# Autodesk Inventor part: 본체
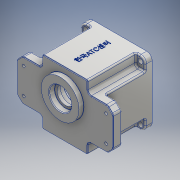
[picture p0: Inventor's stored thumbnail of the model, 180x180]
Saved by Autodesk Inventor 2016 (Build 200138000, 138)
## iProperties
Created: 2017-01
Part Number: 본체
Material: 알루미늄 6061
Document SubType Name: Modeling
Designer: Owner
Density: 2.7 g/cm^3
Appearance: 알루미늄 - 평지
Mass: 874.022 g
Surface Area: 769.042 cm^2
Volume: 323.712 cm^3
Author: Owner
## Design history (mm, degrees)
sketch "스케치1"
  geometry: L1 (47, 47)-(-47, 47); L2 (-47, 47)-(-47, -47); L3 (-47, -47)-(47, -47); L4 (47, -47)-(47, 47); L5 (47, 47)-(-47, -47); L6 (-47, 47)-(47, -47); 1 further point
  constraints: 12 end point, 2 midpoint, 2 parallel, 1 horizontal, 1 perpendicular
  dimensions: "d0" = 94 distance of L2.end L3.end; "d1" = 94 distance of L1.end L2.end
extrude "돌출1" new body sketch "스케치1" distance "d2" = 80; taper "d3" = 0 deg
sketch "스케치2"
  geometry: L1 (0, 0)-(85.477, 0); L2 (9, 0)-(9, 40); L3 (9, 40)-(71, 40); L4 (71, 40)-(71, 43); L5 (71, 43)-(80, 43); L6 (80, 43)-(80, 0); L7 (80, -47)-(80, 47) reference; L8 (0, -47)-(0, 47) reference; L9 (9, 0)-(80, 0)
  constraints: 14 end point, 3 perpendicular, 2 vertical, 1 collinear, 1 horizontal, 1 midpoint, 1 point on line
  dimensions: "d4" = 86 diameter of L5 L1; "d5" = 80 diameter of L3 L1; "d6" = 9 distance of L4.end L5.end; "d7" = 9 distance between parallel lines of L8 L2
revolve "회전1" sketch "스케치2" stored, may be unused: angle "d8" = 90 deg
sketch "스케치3"
  geometry: C1 r 21 at (0, -11); C2 r 15 at (0, 20); 1 further point
  constraints: 2 centre point, 2 vertical alignment
  dimensions: "d9" = 11 distance of point (0, 0) C1.centre; "d10" = 42 diameter of C1; "d13" = 20 distance of C2.centre point (0, 0); "d14" = 30 diameter of C2
extrude "돌출2" join sketch "스케치3" distance "d11" = 7; taper "d12" = 0 deg
hole "구멍1" diameter "d17" = 25; stored, may be unused: countersink angle "d21" = 90 deg, drill point angle "d23" = 118 deg; dims "d15" = 10, "d16" = 10, "d18" = 6, "d19" = 35, "d20" = 10, "d22" = 8
hole "구멍2" diameter "d26" = 19; stored, may be unused: countersink angle "d30" = 90 deg, drill point angle "d32" = 0 deg; dims "d27" = 6, "d28" = 22, "d29" = 7, "d31" = 8, "d33" = 10, "d34" = 10
sketch "스케치5"
  geometry: L1 (-47, 47)-(47, 47) reference; L2 (47, 47)-(47, -47) reference; L3 (47, -47)-(-47, -47) reference; L4 (-47, -47)-(-47, 47) reference; L5 (-33, 47)-(33, 47); L6 (33, 47)-(33, -47); L7 (33, -47)-(-33, -47); L8 (-33, -47)-(-33, 47); L9 (-33, 47)-(33, -47); L10 (33, 47)-(-33, -47); L11 (47, 47)-(47, -47) reference; L12 (-47, 30)-(47, 30); L13 (47, 30)-(47, -30); L14 (47, -30)-(-47, -30); L15 (-47, -30)-(-47, 30); L16 (-47, 30)-(47, -30); L17 (47, 30)-(-47, -30); 1 further point
  constraints: 24 end point, 4 midpoint, 4 parallel, 2 horizontal, 2 perpendicular, 1 horizontal alignment, 1 point on line
  dimensions: "d37" = 66 distance of L5.start L5.end; "d38" = 60 distance of L14.end L12.start
extrude "돌출3" cut sketch "스케치5" distance "d39" = 70; taper "d40" = 0 deg
sketch "스케치6"
  geometry: L1 (70, 30)-(70, -30); L2 (-70, -30)-(-70, 30); L3 (-70, 30)-(70, -30); L4 (70, 30)-(-70, -30); L5 (-47, -30)-(-47, 30) reference; L6 (47, 30)-(47, -30) reference; L7 (-47, 30)-(-47, -30); L8 (-70, 30)-(-47, 30); L9 (47, 30)-(70, 30); L10 (70, -30)-(47, -30); L11 (-47, -30)-(-70, -30); 1 further point
  constraints: 20 end point, 6 equal length, 2 horizontal, 2 midpoint, 2 perpendicular, 1 horizontal alignment
  dimensions: "d41" = 140 distance of L2.end L1.start
extrude "돌출4" join sketch "스케치6" distance "d42" = 13; taper "d43" = 0 deg
sketch "스케치7"
  geometry: C1 r 12.5 at (0, 11) reference; C2 r 27.5 at (0, 11); 1 further point
  constraints: 1 centre point, 1 coincident
  dimensions: "d44" = 55 diameter of C2
extrude "돌출5" join sketch "스케치7" distance "d45" = 7; taper "d46" = 0 deg
hole "구멍3" diameter "d49" = 32; stored, may be unused: countersink angle "d53" = 90 deg, drill point angle "d55" = 0 deg; dims "d50" = 6, "d51" = 22, "d52" = 7, "d54" = 8, "d56" = 10, "d57" = 10
sketch "스케치8" dims "d58" = 72
  geometry: C1 r 40 at (0, 0) reference; A1 r 4 centre (-36, 0) between (-35.852, -3.997) and (-35.852, 3.997); A2 r 40 centre (0, 0) between (-39.148, -8.214) and (-39.148, 8.214) reference; A3 r 3.5 centre (-35.722, -7.495) between (-35.852, -3.997) and (-39.148, -8.214); A4 r 3.5 centre (-35.722, 7.495) between (-39.148, 8.214) and (-35.852, 3.997); 2 further points
  constraints: 8 point on circle, 4 tangent, 3 centre point, 2 horizontal alignment, 1 coincident, 2 other
  dimensions: "d59" = 8 diameter of A1; "d60" = 7 diameter of A3; "d61" = 7 diameter of A4
extrude "돌출6" join sketch "스케치8" stored distance "d62" = 7; taper "d63" = 0 deg
hole "구멍4" diameter "d66" = 3.242; stored, may be unused: countersink angle "d70" = 90 deg, drill point angle "d72" = 118 deg; dims "d64" = 10, "d65" = 10, "d67" = 7, "d68" = 22, "d69" = 7, "d71" = 9
fillet "모깎기1" dims "d73" = 8
sketch "스케치9"
  geometry: 2 further points
  dimensions: "d74" = 40 horizontal distance of point (-40, -40) point (0, 0); "d75" = 40 horizontal distance of point (0, 0) point (-40, -40)
hole "구멍5" sketch "스케치9" at (-40, -40) diameter "d76" = 7; stored, may be unused: countersink angle "d80" = 90 deg, drill point angle "d82" = 118 deg; dims "d77" = 7, "d78" = 22, "d79" = 7, "d81" = 7
chamfer "모따기1" distance "d86" = 8; stored, may be unused: second distance "d87" = 2, angle "d88" = 45 deg
sketch "스케치11"
  geometry: 2 further points
  dimensions: "d92" = 19 vertical distance of point (0, 0) point (-60, -19); "d93" = 60 horizontal distance of point (0, 0) point (-60, -19)
hole "구멍6" sketch "스케치11" at (-60, -19) diameter "d94" = 4; stored, may be unused: countersink angle "d98" = 90 deg, drill point angle "d100" = 118 deg; dims "d95" = 7, "d96" = 10, "d97" = 4, "d99" = 7
fillet "모깎기3" dims "d102" = 2
fillet "모깎기6" dims "d105" = 5
fillet "모깎기7" dims "d106" = 2
fillet "모깎기8" dims "d107" = 5
fillet "모깎기9" dims "d108" = 2
fillet "모깎기10" dims "d109" = 2
fillet "모깎기11" dims "d110" = 0.3
chamfer "모따기2" distance "d111" = 1; stored, may be unused: second distance "d112" = 2, angle "d113" = 45 deg
sketch "스케치12"
  geometry: L1 (33, -45)-(33, -35) reference; L2 (38, -30)-(59.929, -30) reference; L3 (68.536, -23.464)-(63.464, -28.536) reference; L4 (70, -19.929)-(70, 19.929) reference; L5 (63.464, 28.536)-(68.536, 23.464) reference; L6 (59.929, 30)-(38, 30) reference; L7 (33, 35)-(33, 45) reference; L8 (-31, 47)-(31, 47) reference; L9 (-33, 45)-(-33, 35) reference; L10 (-38, 30)-(-59.929, 30) reference; L11 (-68.536, 23.464)-(-63.464, 28.536) reference; L12 (-70, 19.929)-(-70, -19.929) reference; L13 (-63.464, -28.536)-(-68.536, -23.464) reference; L14 (-59.929, -30)-(-38, -30) reference; L15 (-33, -35)-(-33, -45) reference; L16 (31, -47)-(-31, -47) reference; L17 (-32, -45)-(-32, -35); L18 (-38, -29)-(-59.929, -29); L19 (-62.757, -27.828)-(-67.828, -22.757); L20 (-69, -19.929)-(-69, 19.929); L21 (-67.828, 22.757)-(-62.757, 27.828); L22 (-59.929, 29)-(-38, 29); L23 (-32, 35)-(-32, 45); L24 (-31, 46)-(31, 46); L25 (32, 45)-(32, 35); L26 (38, 29)-(59.929, 29); L27 (62.757, 27.828)-(67.828, 22.757); L28 (69, 19.929)-(69, -19.929); L29 (67.828, -22.757)-(62.757, -27.828); L30 (59.929, -29)-(38, -29); L31 (32, -35)-(32, -45); L32 (31, -46)-(-31, -46); C1 r 2 at (60, -19) reference; C2 r 2 at (60, 19) reference; C3 r 2 at (-60, -19) reference; C4 r 2 at (-60, 19) reference; C5 r 27.8 at (0, 11) reference; A1 r 2 centre (31, -45) between (31, -47) and (33, -45) reference; A2 r 5 centre (38, -35) between (38, -30) and (33, -35) reference; A3 r 5 centre (59.929, -25) between (59.929, -30) and (63.464, -28.536) reference; A4 r 5 centre (65, -19.929) between (68.536, -23.464) and (70, -19.929) reference; A5 r 5 centre (65, 19.929) between (70, 19.929) and (68.536, 23.464) reference; A6 r 5 centre (59.929, 25) between (63.464, 28.536) and (59.929, 30) reference; A7 r 5 centre (38, 35) between (33, 35) and (38, 30) reference; A8 r 2 centre (31, 45) between (33, 45) and (31, 47) reference; A9 r 2 centre (-31, 45) between (-31, 47) and (-33, 45) reference; A10 r 5 centre (-38, 35) between (-38, 30) and (-33, 35) reference; A11 r 5 centre (-59.929, 25) between (-59.929, 30) and (-63.464, 28.536) reference; A12 r 5 centre (-65, 19.929) between (-68.536, 23.464) and (-70, 19.929) reference; A13 r 5 centre (-65, -19.929) between (-70, -19.929) and (-68.536, -23.464) reference; A14 r 5 centre (-59.929, -25) between (-63.464, -28.536) and (-59.929, -30) reference; A15 r 5 centre (-38, -35) between (-33, -35) and (-38, -30) reference; A16 r 2 centre (-31, -45) between (-33, -45) and (-31, -47) reference; A17 r 1 centre (-31, -45) between (-32, -45) and (-31, -46); A18 r 6 centre (-38, -35) between (-32, -35) and (-38, -29); A19 r 4 centre (-59.929, -25) between (-62.757, -27.828) and (-59.929, -29); A20 r 4 centre (-65, -19.929) between (-69, -19.929) and (-67.828, -22.757); A21 r 4 centre (-65, 19.929) between (-67.828, 22.757) and (-69, 19.929); A22 r 4 centre (-59.929, 25) between (-59.929, 29) and (-62.757, 27.828); A23 r 6 centre (-38, 35) between (-38, 29) and (-32, 35); A24 r 1 centre (-31, 45) between (-31, 46) and (-32, 45); A25 r 1 centre (31, 45) between (32, 45) and (31, 46); A26 r 6 centre (38, 35) between (32, 35) and (38, 29); A27 r 4 centre (59.929, 25) between (62.757, 27.828) and (59.929, 29); A28 r 4 centre (65, 19.929) between (69, 19.929) and (67.828, 22.757); A29 r 4 centre (65, -19.929) between (67.828, -22.757) and (69, -19.929); A30 r 4 centre (59.929, -25) between (59.929, -29) and (62.757, -27.828); A31 r 6 centre (38, -35) between (38, -29) and (32, -35); A32 r 1 centre (31, -45) between (31, -46) and (32, -45); 1 further point
  constraints: 32 end point, 32 point on circle, 16 centre point, 31 other
  dimensions: "d114" = 1 distance between parallel lines of L16 L32
extrude "돌출7" cut sketch "스케치12" distance "d115" = 1; taper "d116" = 0 deg
sketch "스케치13"
  geometry: L1 (0, 0)-(78, 0) reference; 2 further points
  constraints: 1 vertical alignment, 1 other
  dimensions: "d117" = 40 distance from line of L1 point (39, -40)
feature "엠보싱1" sketch "스케치13" dims "d118" = 0.5, "d119" = 0
fillet "모깎기12" dims "d120" = 2
node "솔리드1"
mirror "대칭1"
pattern_circular "원형 패턴1" dims angle "d84" = 360 deg
mirror "대칭2"
mirror "대칭3"
node "투영된 루프1"
node "투영된 루프2"
